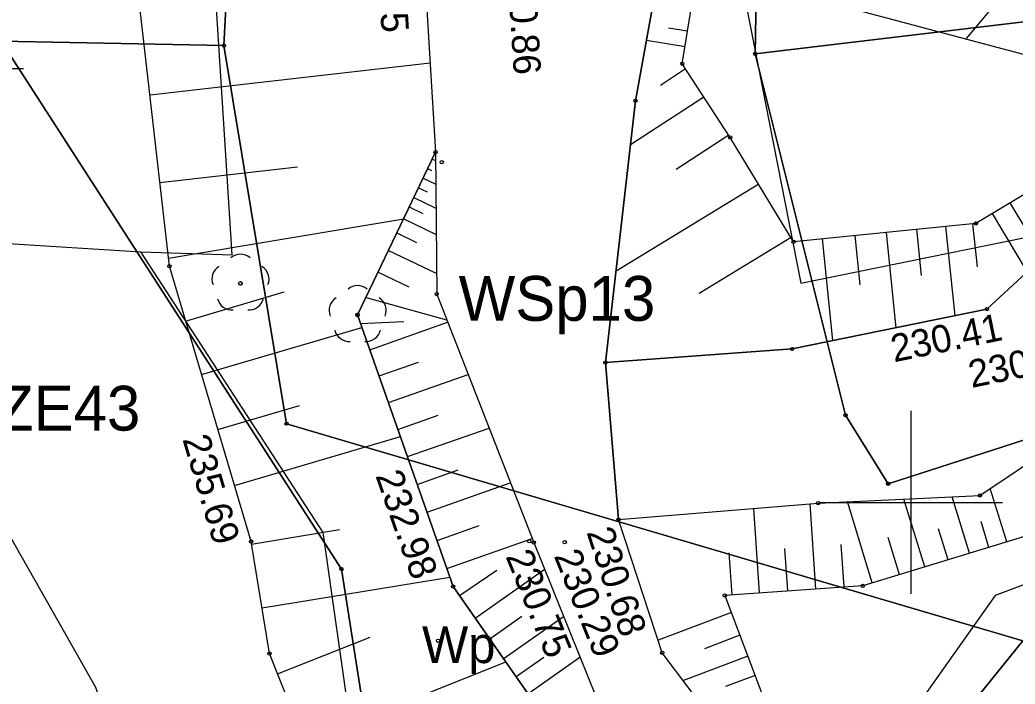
# Model space of a CAD drawing. Extents: x 6596400 to 6597200, y 5539751 to 5540251.
# Drawn here: x 6596725.66 to 6596752.84, y 5540046.04 to 5540064.18 of the extents above; entities that cross this region are included whole.
import ezdxf

# ---------------------------------------------------------------- set-up
doc = ezdxf.new("R2010")
doc.units = 0
for name, color, linetype in [('000 Inne (niezydentyfikowane)', 7, 'Continuous'), ('140-Punkty robocze', 7, 'Continuous'), ('203-punkt graniczny', 7, 'Continuous'), ('210-oznaczenie konturu użytku gruntowego', 7, 'Continuous'), ('217-kontur klasyfikacyjny', 7, 'Continuous'), ('218-kontur użytku gruntowego', 7, 'Continuous'), ('219-działka ewidencyjna', 7, 'Continuous'), ('drzewo liściaste', 7, 'Continuous'), ('Linia obszaru zagospodarowania terenu', 7, 'Continuous'), ('Opis obszaru zagospodarowania terenu', 7, 'Continuous'), ('pikieta sztuczna', 7, 'Continuous'), ('pikieta sztuczna-Atr2', 7, 'Continuous'), ('rzedna-Atr2', 7, 'Continuous'), ('rów melioracyjny (poligon)', 7, 'Continuous'), ('skarpa nieumocniona', 7, 'Continuous'), ('woda płynąca', 7, 'Continuous'), ('Wstawianie ramki sekcyjnej z opisem', 7, 'Continuous'), ('Zakres', 7, 'Continuous')]:
    doc.layers.add(name, color=color, linetype=linetype)

# ---------------------------------------------------------------- blocks, each defined once
blk = doc.blocks.new('203')
blk.add_circle((0, 0), 0.045)
blk = doc.blocks.new('OP021')
blk.add_circle((0, 0), 0.05)
for centre, start, end in [((0, 0.4), 49.272, 130.728), ((-0.38, 0.124), 121.308, 202.548), ((0.38, 0.124), 337.452, 58.692), ((-0.235, -0.324), 193.221, 274.871), ((0.235, -0.324), 265.129, 346.779)]:
    blk.add_arc(centre, 0.4, start, end)
blk = doc.blocks.new('RAMKA500K')
for p, q in [((350, 48.5), (350, 53.5)), ((347.5, 51), (352.5, 51))]:
    blk.add_line(p, q)
blk = doc.blocks.new('PIKIETA')
blk.add_circle((0, 0), 0.045)
blk = doc.blocks.new('PW01')
blk.add_circle((0, 0), 0.045)

msp = doc.modelspace()

# ---------------------------------------------------------------- linework, layer by layer
at = {"layer": '000 Inne (niezydentyfikowane)'}
for p, q in [((6596729.21, 5540062.13), (6596736.86, 5540063.01)), ((6596729.48, 5540059.74), (6596733.24, 5540060.17)), ((6596729.71, 5540057.67), (6596736.14, 5540058.75)), ((6596730.18, 5540055.95), (6596732.87, 5540056.75)), ((6596730.62, 5540054.49), (6596735, 5540055.78)), ((6596731.06, 5540052.99), (6596733.29, 5540053.65)), ((6596731.52, 5540051.46), (6596736.05, 5540052.8)), ((6596751.59, 5540049.61), (6596751.12, 5540051.15)), ((6596752.61, 5540049.92), (6596752.16, 5540051.38)), ((6596747.4, 5540048.63), (6596747.24, 5540050.96)), ((6596748.94, 5540048.8), (6596748.26, 5540051.02)), ((6596750.37, 5540049.24), (6596749.8, 5540051.09)), ((6596745.86, 5540048.53), (6596745.7, 5540050.83)), ((6596752.12, 5540049.77), (6596751.91, 5540050.48)), ((6596731.98, 5540049.86), (6596734.39, 5540050.26)), ((6596749.68, 5540049.02), (6596749.37, 5540050.04)), ((6596751.01, 5540049.43), (6596750.75, 5540050.28)), ((6596748.17, 5540048.69), (6596748.09, 5540049.85)), ((6596745.11, 5540048.47), (6596745.03, 5540049.62)), ((6596746.63, 5540048.58), (6596746.55, 5540049.74)), ((6596732.27, 5540048.12), (6596737.4, 5540048.96)), ((6596745.09, 5540047.99), (6596743.09, 5540047.24)), ((6596732.69, 5540046.32), (6596735.22, 5540047.32)), ((6596745.32, 5540047.37), (6596744.36, 5540047)), ((6596745.54, 5540046.8), (6596743.78, 5540046.13)), ((6596733.43, 5540044.45), (6596738.93, 5540046.64)), ((6596745.74, 5540046.27), (6596744.93, 5540045.97))]:
    msp.add_line(p, q, dxfattribs=at)
for points in [[(6596753.75, 5540066.36), (6596751.5, 5540063.67)], [(6596743.89, 5540063.87), (6596743.37, 5540063.95)], [(6596743.83, 5540063.44), (6596742.77, 5540063.62)], [(6596743.84, 5540062.84), (6596743.15, 5540062.39)], [(6596744.34, 5540062.07), (6596742.33, 5540060.77)], [(6596745.02, 5540061.03), (6596743.58, 5540060.09)], [(6596736.92, 5540060.38), (6596737.01, 5540060.34)], [(6596736.79, 5540060.12), (6596736.9, 5540060.07)], [(6596736.67, 5540059.86), (6596737.02, 5540059.69)], [(6596736.54, 5540059.59), (6596736.78, 5540059.48)], [(6596745.84, 5540059.69), (6596741.94, 5540057.32)], [(6596736.42, 5540059.33), (6596737.02, 5540059.04)], [(6596736.29, 5540059.07), (6596736.66, 5540058.89)], [(6596752.7, 5540059.18), (6596753.15, 5540058.43)], [(6596736.14, 5540058.75), (6596737.03, 5540058.32)], [(6596752.21, 5540058.89), (6596753.17, 5540057.29)], [(6596750.15, 5540058.46), (6596750.27, 5540057.2)], [(6596750.94, 5540058.54), (6596751.19, 5540056.1)], [(6596751.68, 5540058.61), (6596751.8, 5540057.43)], [(6596735.95, 5540058.36), (6596736.49, 5540058.1)], [(6596746.72, 5540058.24), (6596744.21, 5540056.71)], [(6596747.57, 5540058.2), (6596747.85, 5540055.42)], [(6596748.46, 5540058.29), (6596748.6, 5540056.94)], [(6596749.32, 5540058.37), (6596749.58, 5540055.77)], [(6596735.72, 5540057.88), (6596737.04, 5540057.25)], [(6596735.44, 5540057.29), (6596736.28, 5540056.89)], [(6596735.11, 5540056.6), (6596737.31, 5540055.99)], [(6596734.96, 5540055.89), (6596736.14, 5540055.94)], [(6596735.21, 5540055.17), (6596737.34, 5540055.92)], [(6596735.47, 5540054.46), (6596736.54, 5540054.83)], [(6596735.72, 5540053.73), (6596737.9, 5540054.49)], [(6596735.98, 5540052.99), (6596737.08, 5540053.38)], [(6596736.24, 5540052.25), (6596738.47, 5540053.03)], [(6596736.51, 5540051.49), (6596737.63, 5540051.89)], [(6596736.78, 5540050.73), (6596739.05, 5540051.53)], [(6596737.05, 5540049.96), (6596738.2, 5540050.37)], [(6596737.32, 5540049.19), (6596739.65, 5540050.01)], [(6596737.66, 5540048.46), (6596738.68, 5540049.15)], [(6596738.09, 5540047.84), (6596739.98, 5540049.17)], [(6596738.49, 5540047.27), (6596739.37, 5540047.89)], [(6596738.86, 5540046.73), (6596740.5, 5540047.88)], [(6596739.21, 5540046.24), (6596739.97, 5540046.77)], [(6596739.53, 5540045.77), (6596740.95, 5540046.77)]]:
    msp.add_lwpolyline(points, dxfattribs=at)
at = {"layer": '217-kontur klasyfikacyjny'}
for points in [[(6596734.44, 5540049.18), (6596725.14, 5540063.6)], [(6596736.14, 5540038.34), (6596734.44, 5540049.18)], [(6596753.05, 5540047.22), (6596750.47, 5540044.03)]]:
    msp.add_lwpolyline(points, dxfattribs=at)
at = {"layer": '218-kontur użytku gruntowego'}
for points in [[(6596731.78, 5540074), (6596731.23, 5540063.48)], [(6596731.23, 5540063.48), (6596731.78, 5540074)], [(6596745.74, 5540063.25), (6596745.91, 5540073.23)], [(6596745.91, 5540073.23), (6596745.74, 5540063.25)], [(6596753.08, 5540064.13), (6596745.74, 5540063.25)], [(6596745.74, 5540063.25), (6596753.08, 5540064.13)], [(6596734.44, 5540049.18), (6596725.14, 5540063.6)], [(6596731.23, 5540063.48), (6596725.14, 5540063.6)], [(6596725.14, 5540063.6), (6596734.44, 5540049.18)], [(6596725.14, 5540063.6), (6596731.23, 5540063.48)], [(6596731.23, 5540063.48), (6596732.94, 5540053.15)], [(6596732.94, 5540053.15), (6596731.23, 5540063.48)], [(6596748.21, 5540053.38), (6596745.74, 5540063.25)], [(6596745.74, 5540063.25), (6596748.21, 5540053.38)], [(6596786.08, 5540063.35), (6596749.37, 5540051.51)], [(6596749.37, 5540051.51), (6596786.08, 5540063.35)], [(6596749.37, 5540051.51), (6596748.21, 5540053.38)], [(6596748.21, 5540053.38), (6596749.37, 5540051.51)], [(6596732.94, 5540053.15), (6596753.05, 5540047.22)], [(6596753.05, 5540047.22), (6596732.94, 5540053.15)], [(6596736.14, 5540038.34), (6596734.44, 5540049.18)], [(6596734.44, 5540049.18), (6596736.14, 5540038.34)], [(6596753.05, 5540047.22), (6596750.47, 5540044.03)], [(6596750.47, 5540044.03), (6596753.05, 5540047.22)]]:
    msp.add_lwpolyline(points, dxfattribs=at)
at = {"layer": '219-działka ewidencyjna'}
for points in [[(6596731.23, 5540063.48), (6596731.78, 5540074)], [(6596745.74, 5540063.25), (6596745.91, 5540073.23)], [(6596745.74, 5540063.25), (6596753.08, 5540064.13)], [(6596725.14, 5540063.6), (6596731.23, 5540063.48)], [(6596734.44, 5540049.18), (6596725.14, 5540063.6)], [(6596732.94, 5540053.15), (6596731.23, 5540063.48)], [(6596748.21, 5540053.38), (6596745.74, 5540063.25)], [(6596749.37, 5540051.51), (6596786.08, 5540063.35)], [(6596749.37, 5540051.51), (6596748.21, 5540053.38)], [(6596753.05, 5540047.22), (6596732.94, 5540053.15)], [(6596736.14, 5540038.34), (6596734.44, 5540049.18)], [(6596750.47, 5540044.03), (6596753.05, 5540047.22)]]:
    msp.add_lwpolyline(points, dxfattribs=at)
at = {"layer": 'Linia obszaru zagospodarowania terenu'}
for points in [[(6596720.263, 5540058.387), (6596728.96, 5540057.84), (6596731.45, 5540057.76), (6596731.02, 5540064.64), (6596745.49, 5540064.58), (6596746.99, 5540056.99), (6596772.84, 5540062.25), (6596786.21, 5540064.83), (6596807.99, 5540057.58), (6596818.837, 5540049.192)], [(6596816.371, 5540045.853), (6596805.78, 5540054.39), (6596786.09, 5540061.13), (6596752.3, 5540048.46), (6596750.16, 5540045.43), (6596750.4, 5540037.69), (6596745.15, 5540037.73), (6596747.098, 5540030.366)], [(6596741.654, 5540031.114), (6596739.85, 5540039.37), (6596735.5, 5540039.24), (6596733.94, 5540050.18), (6596728.96, 5540057.84)]]:
    msp.add_lwpolyline(points, dxfattribs=at)
at = {"layer": 'rzedna-Atr2'}
msp.add_lwpolyline([(6596720.2, 5540067.11), (6596722.61, 5540062.85), (6596725.756, 5540062.85)], dxfattribs=at)
at = {"layer": 'rów melioracyjny (poligon)'}
msp.add_lwpolyline([(6596820.208, 5540051.05), (6596817.24, 5540053.08), (6596812.31, 5540056.77), (6596808.36, 5540059.4), (6596802.55, 5540062.58), (6596795.13, 5540065.25), (6596788.99, 5540067.23), (6596782.3, 5540068.04), (6596775.52, 5540068.1), (6596768.51, 5540067.33), (6596764.82, 5540065.79), (6596761.35, 5540063.62), (6596758.63, 5540061.34), (6596754.58, 5540058.6), (6596752.07, 5540056.28), (6596746.75, 5540055.19), (6596741.65, 5540054.82), (6596742.01, 5540050.53), (6596747.46, 5540050.98), (6596751.88, 5540051.19), (6596756.01, 5540053.96), (6596757.53, 5540054.97), (6596761.73, 5540059.12)], dxfattribs=at)
at = {"layer": 'skarpa nieumocniona'}
for points in [[(6596733.94, 5540086.32), (6596732.43, 5540082.43), (6596735.19, 5540080.23), (6596736.14, 5540074.83), (6596737.01, 5540060.57), (6596734.88, 5540056.12), (6596737.49, 5540048.7), (6596742.37, 5540041.71), (6596738.78, 5540039.69), (6596738.22, 5540031.96), (6596734.92, 5540032.83), (6596735.24, 5540039.91), (6596732.47, 5540046.87), (6596731.97, 5540049.93), (6596729.74, 5540057.45), (6596728.56, 5540067.81), (6596728.25, 5540071.52), (6596725.74, 5540083.5), (6596726.85, 5540087.53)], [(6596733.94, 5540086.32), (6596732.43, 5540082.43), (6596735.19, 5540080.23), (6596736.14, 5540074.83), (6596737.01, 5540060.57), (6596734.88, 5540056.12), (6596737.49, 5540048.7), (6596742.37, 5540041.71), (6596738.78, 5540039.69), (6596738.22, 5540031.96), (6596734.92, 5540032.83), (6596735.24, 5540039.91), (6596732.47, 5540046.87), (6596731.97, 5540049.93), (6596729.74, 5540057.45), (6596728.56, 5540067.81), (6596728.25, 5540071.52), (6596725.74, 5540083.5), (6596726.85, 5540087.53)], [(6596756.22, 5540066.9), (6596754.09, 5540066.07), (6596752.07, 5540067.76), (6596750.47, 5540074), (6596751.32, 5540077.29), (6596748.52, 5540081.03), (6596740.72, 5540079.85), (6596740.68, 5540078.45), (6596742.94, 5540074), (6596746.51, 5540071.34), (6596747.03, 5540064.86), (6596756.25, 5540062.4), (6596756.95, 5540064.41)], [(6596756.22, 5540066.9), (6596754.09, 5540066.07), (6596752.07, 5540067.76), (6596750.47, 5540074), (6596751.32, 5540077.29), (6596748.52, 5540081.03), (6596740.72, 5540079.85), (6596740.68, 5540078.45), (6596742.94, 5540074), (6596746.51, 5540071.34), (6596747.03, 5540064.86), (6596756.25, 5540062.4), (6596756.95, 5540064.41)], [(6596756.16, 5540061.25), (6596751.77, 5540058.62), (6596746.79, 5540058.12), (6596745.06, 5540060.97), (6596743.75, 5540062.98), (6596744.34, 5540066.61), (6596742.94, 5540074), (6596740.68, 5540078.45), (6596741.68, 5540074.92), (6596743.25, 5540066.3), (6596742.47, 5540061.97), (6596741.65, 5540054.82), (6596746.75, 5540055.19), (6596752.07, 5540056.28), (6596754.58, 5540058.6), (6596758.63, 5540061.34)], [(6596756.16, 5540061.25), (6596751.77, 5540058.62), (6596746.79, 5540058.12), (6596745.06, 5540060.97), (6596743.75, 5540062.98), (6596744.34, 5540066.61), (6596742.94, 5540074), (6596740.68, 5540078.45), (6596741.68, 5540074.92), (6596743.25, 5540066.3), (6596742.47, 5540061.97), (6596741.65, 5540054.82), (6596746.75, 5540055.19), (6596752.07, 5540056.28), (6596754.58, 5540058.6), (6596758.63, 5540061.34)], [(6596747.16, 5540032.77), (6596746.58, 5540032.45), (6596744.67, 5540040.28), (6596742.37, 5540041.71), (6596737.49, 5540048.7), (6596734.88, 5540056.12), (6596737.01, 5540060.57), (6596737.04, 5540056.69), (6596739.69, 5540049.9), (6596742.87, 5540042.02), (6596744.95, 5540040.49)], [(6596747.16, 5540032.77), (6596746.58, 5540032.45), (6596744.67, 5540040.28), (6596742.37, 5540041.71), (6596737.49, 5540048.7), (6596734.88, 5540056.12), (6596737.01, 5540060.57), (6596737.04, 5540056.69), (6596739.69, 5540049.9), (6596742.87, 5540042.02), (6596744.95, 5540040.49)], [(6596764.63, 5540056.07), (6596757.72, 5540051.48), (6596748.68, 5540048.72), (6596744.91, 5540048.46), (6596747.72, 5540041.03), (6596748.61, 5540037.56), (6596751.13, 5540029.81), (6596749.69, 5540030.01), (6596747.71, 5540037.43), (6596746.88, 5540041.11), (6596746.88, 5540042.02), (6596743.2, 5540046.89), (6596742.01, 5540050.53), (6596747.46, 5540050.98), (6596751.88, 5540051.19), (6596756.01, 5540053.96), (6596757.53, 5540054.97), (6596761.73, 5540059.12)], [(6596764.63, 5540056.07), (6596757.72, 5540051.48), (6596748.68, 5540048.72), (6596744.91, 5540048.46), (6596747.72, 5540041.03), (6596748.61, 5540037.56), (6596751.13, 5540029.81), (6596749.69, 5540030.01), (6596747.71, 5540037.43), (6596746.88, 5540041.11), (6596746.88, 5540042.02), (6596743.2, 5540046.89), (6596742.01, 5540050.53), (6596747.46, 5540050.98), (6596751.88, 5540051.19), (6596756.01, 5540053.96), (6596757.53, 5540054.97), (6596761.73, 5540059.12)]]:
    msp.add_lwpolyline(points, close=True, dxfattribs=at)
at = {"layer": 'woda płynąca'}
for points in [[(6596746.88, 5540042.02), (6596743.2, 5540046.89), (6596742.01, 5540050.53), (6596741.65, 5540054.82), (6596742.47, 5540061.97), (6596743.25, 5540066.3), (6596741.68, 5540074.92), (6596740.68, 5540078.45), (6596740.72, 5540079.85), (6596740.91, 5540084.82), (6596741.25, 5540084.94), (6596740.92, 5540088.42), (6596742.42, 5540096.36), (6596743.6, 5540103.66), (6596744.49, 5540107.55), (6596747.66, 5540110.25), (6596750.9, 5540111.08), (6596759.95, 5540110.31), (6596765.11, 5540108.34), (6596769.44, 5540104.84), (6596775.99, 5540100.07), (6596783.39, 5540096.06), (6596790.43, 5540094.51)], [(6596736.53, 5540085.88), (6596736.56, 5540080.1), (6596736.48, 5540078.77), (6596736.14, 5540074.83), (6596737.01, 5540060.57), (6596737.04, 5540056.69), (6596739.69, 5540049.9), (6596742.87, 5540042.02), (6596744.95, 5540040.49), (6596747.16, 5540032.77), (6596747.69, 5540030.285)]]:
    msp.add_lwpolyline(points, dxfattribs=at)
at = {"layer": 'Zakres'}
msp.add_lwpolyline([(6596822.22, 5540097.5), (6596800.39, 5540105.4), (6596755.76, 5540121.45), (6596697.73, 5540120.74), (6596659.35, 5540133.92), (6596647.64, 5540109.28), (6596697.73, 5540077), (6596721.01, 5540057.77), (6596727.72, 5540045.95), (6596731.95, 5540033.61), (6596741.17, 5540031.18), (6596755.59, 5540029.2), (6596757.85, 5540044.22), (6596787.25, 5540055.04), (6596806.3, 5540048.33), (6596813.97, 5540042.6), (6596833.15, 5540068.58), (6596822.3, 5540077.75)], close=True, dxfattribs=at)

# ---------------------------------------------------------------- block references
at = {"layer": '140-Punkty robocze'}
for p in [(6596743.75, 5540062.98), (6596742.47, 5540061.97), (6596745.06, 5540060.97), (6596737.01, 5540060.57), (6596737.18, 5540060.29), (6596751.77, 5540058.62), (6596746.79, 5540058.12), (6596729.74, 5540057.45), (6596731.68, 5540056.98), (6596737.04, 5540056.69), (6596752.07, 5540056.28), (6596734.88, 5540056.12), (6596746.75, 5540055.19), (6596741.65, 5540054.82), (6596751.88, 5540051.19), (6596747.46, 5540050.98), (6596742.01, 5540050.53), (6596731.97, 5540049.93), (6596739.57, 5540049.94), (6596739.69, 5540049.9), (6596740.54, 5540049.91), (6596737.49, 5540048.7), (6596748.68, 5540048.72), (6596744.91, 5540048.46), (6596737.08, 5540047.22), (6596732.47, 5540046.87), (6596743.2, 5540046.89)]:
    msp.add_blockref('PIKIETA', p, dxfattribs=at)
at = {"layer": '203-punkt graniczny'}
for p in [(6596731.23, 5540063.48), (6596745.74, 5540063.25), (6596748.21, 5540053.38), (6596732.94, 5540053.15), (6596749.37, 5540051.51), (6596734.44, 5540049.18)]:
    msp.add_blockref('203', p, dxfattribs=at)
at = {"layer": 'drzewo liściaste'}
for p in [(6596731.68, 5540056.98), (6596734.88, 5540056.12)]:
    msp.add_blockref('OP021', p, dxfattribs=at)
at = {"layer": 'pikieta sztuczna'}
for p in [(6596752.07, 5540056.28), (6596742.01, 5540050.53), (6596731.97, 5540049.93), (6596739.69, 5540049.9), (6596740.54, 5540049.91), (6596737.49, 5540048.7)]:
    msp.add_blockref('PW01', p, dxfattribs=at)
at = {"layer": 'Wstawianie ramki sekcyjnej z opisem'}
msp.add_blockref('RAMKA500K', (6596400, 5540000), dxfattribs=at)

# ---------------------------------------------------------------- texts
at = {"layer": '210-oznaczenie konturu użytku gruntowego'}
msp.add_text('Wp', height=1, dxfattribs=at).set_placement((6596736.64, 5540046.61))
at = {"layer": 'Opis obszaru zagospodarowania terenu'}
for s, p in [('WSp13', (6596737.64, 5540055.96)), ('ZE43', (6596725.03, 5540052.96))]:
    msp.add_text(s, height=1.225, dxfattribs=at).set_placement(p)
at = {"layer": 'pikieta sztuczna-Atr2'}
for s, rotation, p in [('230.95', 273.491, (6596735.351, 5540066.874)), ('230.86', 273.491, (6596738.961, 5540065.724)), ('230.41', 11.579, (6596749.531, 5540054.825)), ('230.71', 11.579, (6596751.651, 5540054.125)), ('235.69', 286.517, (6596730.091, 5540052.727)), ('232.98', 289.379, (6596735.362, 5540051.731)), ('230.68', 288.104, (6596741.127, 5540050.187)), ('230.75', 291.977, (6596738.914, 5540049.529)), ('230.29', 291.977, (6596740.234, 5540049.539))]:
    msp.add_text(s, height=0.75, rotation=rotation, dxfattribs=at).set_placement(p)

doc.saveas('drawing.dxf')
